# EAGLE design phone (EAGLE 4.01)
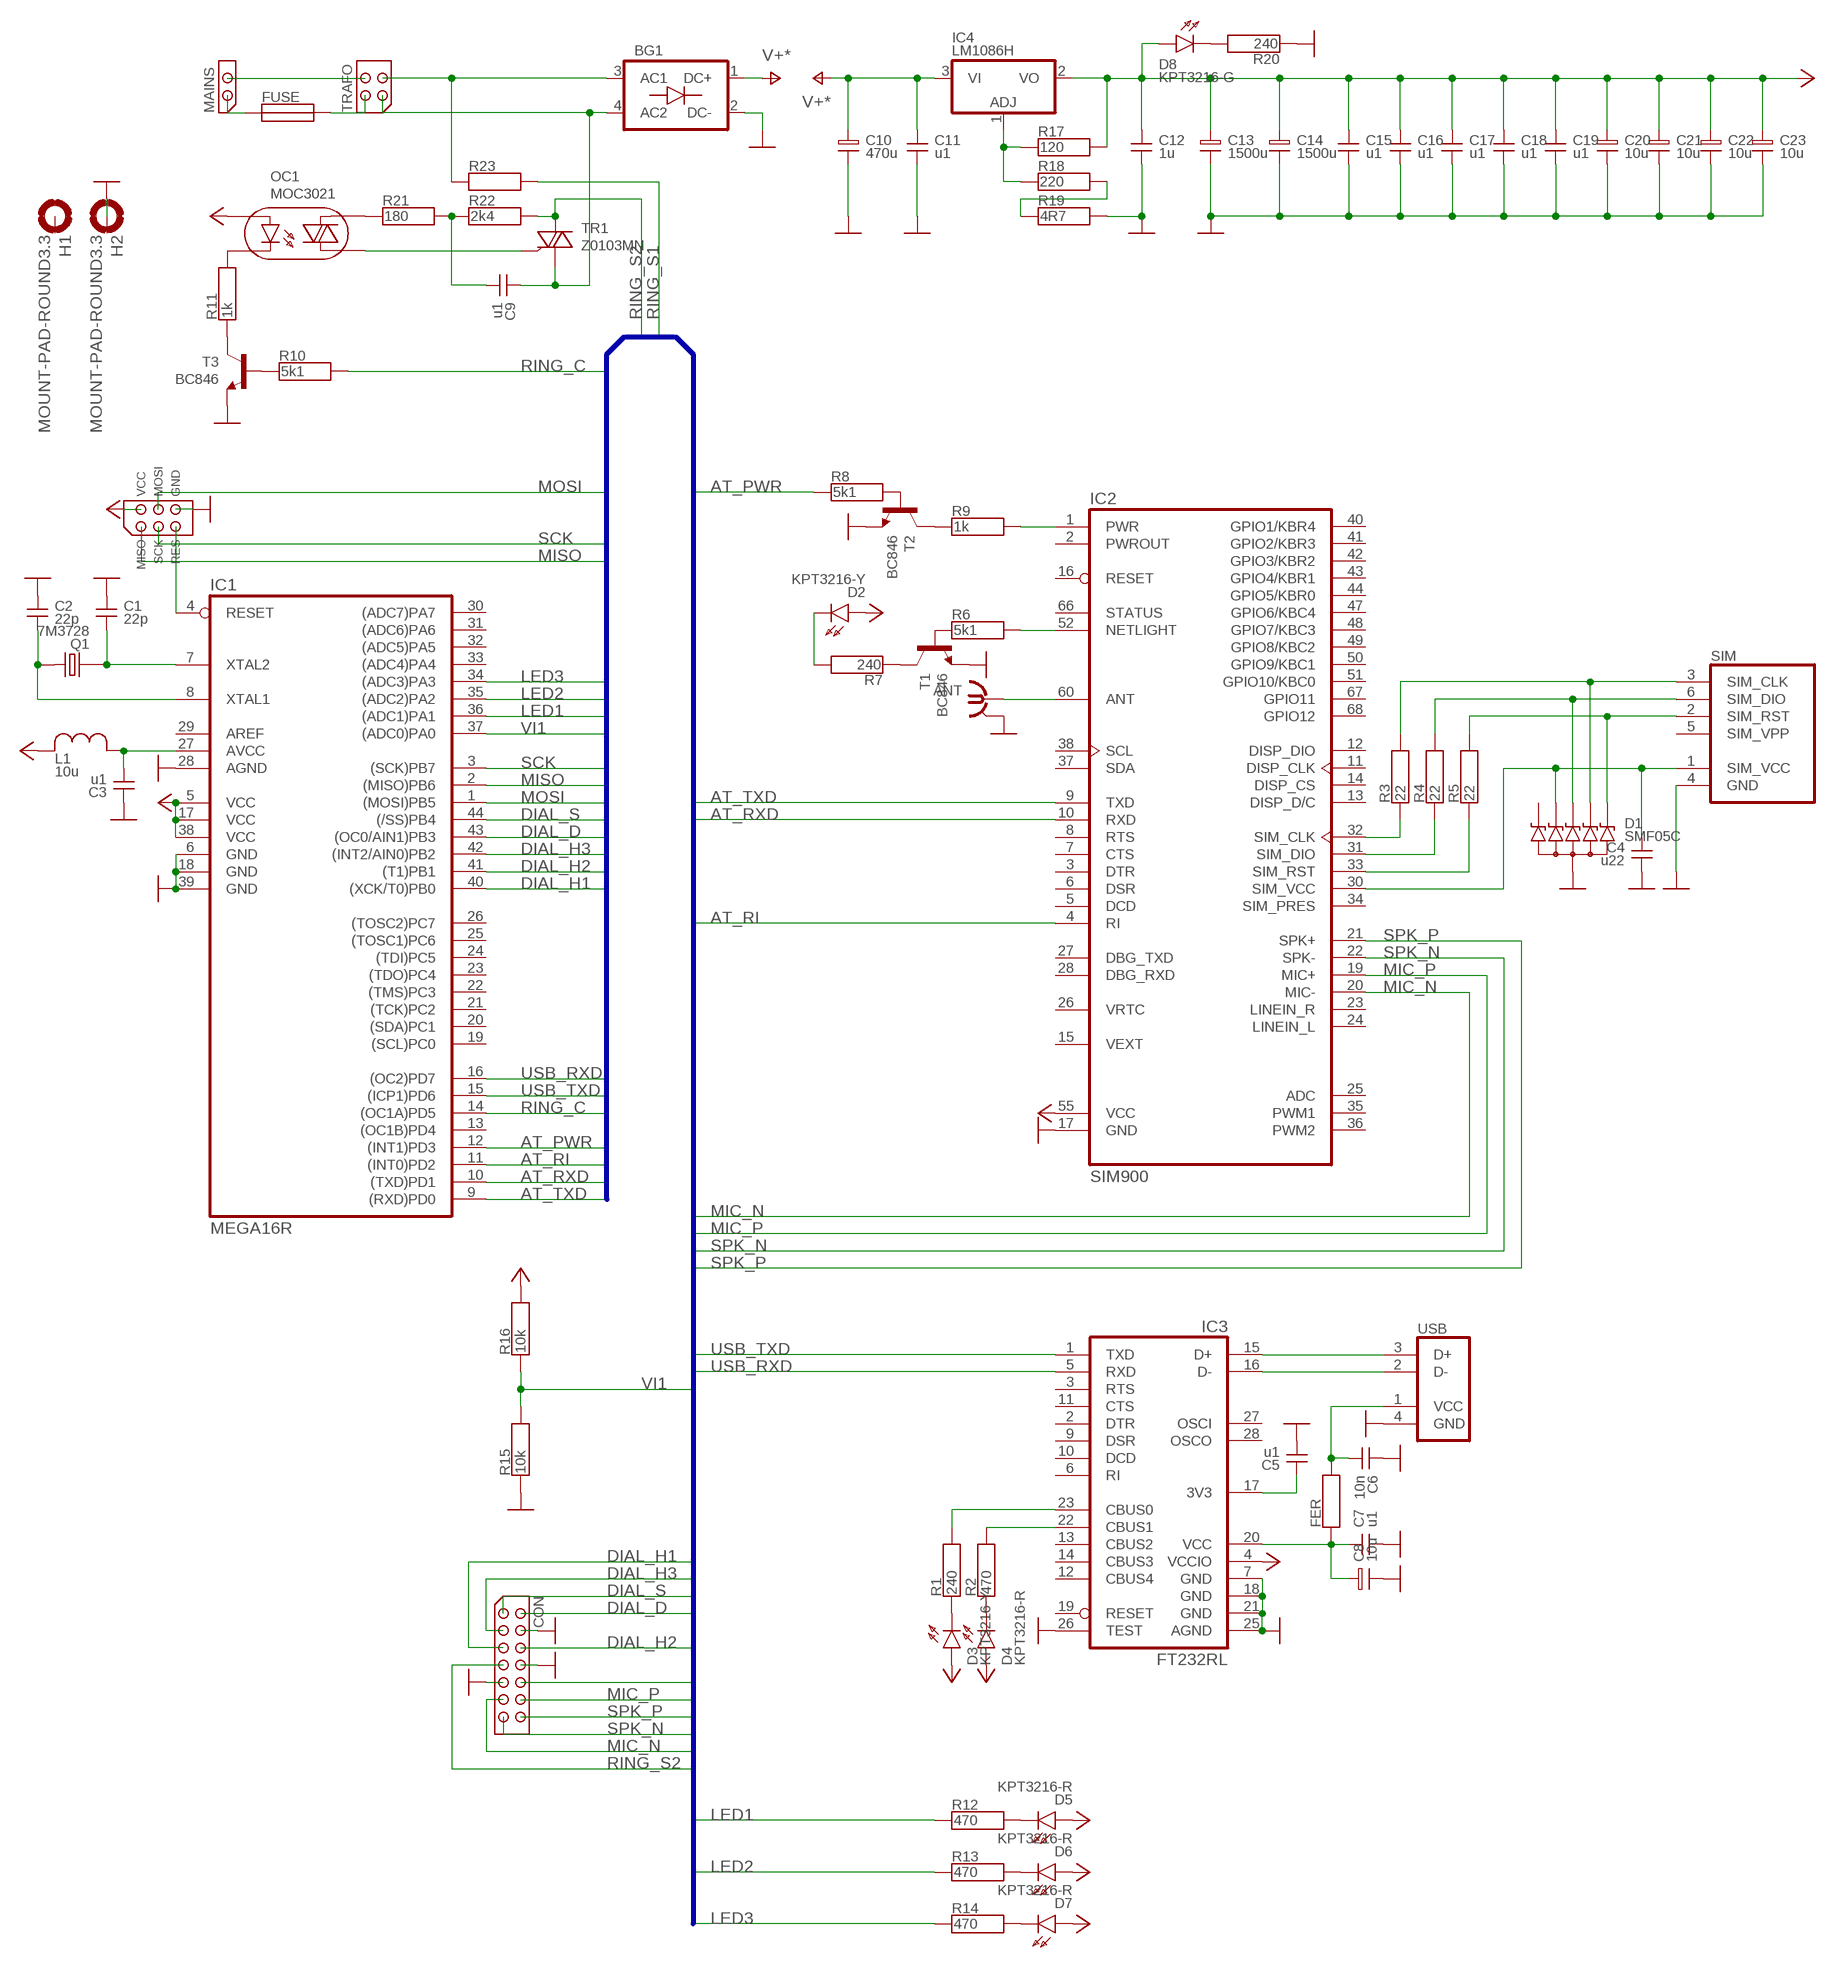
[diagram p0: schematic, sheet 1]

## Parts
ANT  SMAV  [SMAV]
BG1  BGR  [DFXXS]
C1  22p  CAP0805  [0805]
C2  22p  CAP0805  [0805]
C3  u1  CAP0805  [0805]
C4  u22  CAP0805  [0805]
C5  u1  CAP0805  [0805]
C6  10n  CAP0805  [0805]
C7  u1  CAP0805  [0805]
C8  10u  CTA3216  [3216]
C9  u1  CAP0805  [0805]
C10  470u  ELKH  [SMCH]
C11  u1  CAP0805  [0805]
C12  1u  CAP0805  [0805]
C13  1500u  ELKH  [SMCH]
C14  1500u  ELKH  [SMCH]
C15  u1  CAP0805  [0805]
C16  u1  CAP0805  [0805]
C17  u1  CAP0805  [0805]
C18  u1  CAP0805  [0805]
C19  u1  CAP0805  [0805]
C20  10u  CTA3216  [3216]
C21  10u  CTA3216  [3216]
C22  10u  CTA3216  [3216]
C23  10u  CTA3216  [3216]
CON  CON07X2  [CON07X2]
D1  SMF05C  DA5  [SC70-6]
D2  KPT3216-Y  LED1206  [1206]
D3  KPT3216-Y  LED1206  [1206]
D4  KPT3216-R  LED1206  [1206]
D5  KPT3216-R  LED1206  [1206]
D6  KPT3216-R  LED1206  [1206]
D7  KPT3216-R  LED1206  [1206]
D8  KPT3216-G  LED1206  [1206]
FER  RES1206  [1206]
FUSE  FUSE  [FUSE]
H1  MOUNT-PAD-ROUND3.3  [3,3-PAD]
H2  MOUNT-PAD-ROUND3.3  [3,3-PAD]
IC1  MEGA16R  [TQFP44]
IC2  SIM900  [PSP68]
IC3  FT232RL  [SSOP28]
IC4  LM1086H  LM317H  [TO220H]
ISP  ISP6  [CON03X2]
L1  10u  L1206  [1206]
MAINS  N42GP02  [N42GP02]
OC1  MOC3021  OCT  [DIL06]
Q1  7M3728  Q01S  [HC49S]
R1  240  RES0805  [0805]
R2  470  RES0805  [0805]
R3  22  RES0805  [0805]
R4  22  RES0805  [0805]
R5  22  RES0805  [0805]
R6  5k1  RES0805  [0805]
R7  240  RES0805  [0805]
R8  5k1  RES0805  [0805]
R9  1k  RES0805  [0805]
R10  5k1  RES0805  [0805]
R11  1k  RES0805  [0805]
R12  470  RES0805  [0805]
R13  470  RES0805  [0805]
R14  470  RES0805  [0805]
R15  10k  RES0805  [0805]
R16  10k  RES0805  [0805]
R17  120  RES0805  [0805]
R18  220  RES0805  [0805]
R19  4R7  RES0805  [0805]
R20  240  RES0805  [0805]
R21  180  RES0805  [0805]
R22  2k4  RES0805  [0805]
R23  RES03  [02P300IL]
SIM  SIM  [C70710M0060492]
T1  BC846  TSSMDN  [SOT23]
T2  BC846  TSSMDN  [SOT23]
T3  BC846  TSSMDN  [SOT23]
TR1  Z0103MN  TRS  [SOT223]
TRAFO  N42GP04  [N42GP04]
USB  USBBV  [USBBV]

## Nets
AC_6_1: BG1.3(AC1) R23.1 TRAFO.3
AC_6_2: BG1.4(AC2) C9.2 TR1.1(A1) TRAFO.1
AT_PWR: IC1.12((INT1)PD3) R8.1
AT_RI: IC1.11((INT0)PD2) IC2.4(RI)
AT_RXD: IC1.10((TXD)PD1) IC2.10(RXD)
AT_TXD: IC1.9((RXD)PD0) IC2.9(TXD)
AVCC: C3.1 IC1.27(AVCC) L1.2
DIAL_D: CON.2 IC1.43((OC0/AIN1)PB3)
DIAL_H1: CON.5 IC1.40((XCK/T0)PB0)
DIAL_H2: CON.6 IC1.41((T1)PB1)
DIAL_H3: CON.3 IC1.42((INT2/AIN0)PB2)
DIAL_S: CON.1 IC1.44((/SS)PB4)
GND: ANT.2(GND) BG1.2(DC-) C1.2 C2.2 C3.2 C4.1 C5.1 C6.2 C7.1 C8.-(N) C10.N C11.1 C12.1 C13.N C14.N C15.1 C16.1 C17.1 C18.1 C19.1 C20.-(N) C21.-(N) C22.-(N) C23.-(N) CON.4 CON.8 CON.9 D1.2(A) H2.B3,3(MOUNT) IC1.6(GND) IC1.18(GND) IC1.28(AGND) IC1.39(GND) IC2.17(GND) IC3.7(GND) IC3.18(GND) IC3.21(GND) IC3.25(AGND) IC3.26(TEST) ISP.6(GND) R15.1 R19.2 R20.1 SIM.4(GND) T1.2(E) T2.2(E) T3.2(E) USB.4(GND) ; supply symbol labelled GND*
LED1: IC1.36((ADC1)PA1) R12.1
LED2: IC1.35((ADC2)PA2) R13.1
LED3: IC1.34((ADC3)PA3) R14.1
MIC_N: CON.11 IC2.20(MIC-)
MIC_P: CON.12 IC2.19(MIC+)
MISO: IC1.2((MISO)PB6) ISP.1(MISO)
MOSI: IC1.1((MOSI)PB5) ISP.4(MOSI)
N$1: C2.1 IC1.8(XTAL1) Q1.2
N$2: MAINS.2 TRAFO.4
N$3: C1.1 IC1.7(XTAL2) Q1.1
N$4: D2.2(C) R7.2
N$5: FUSE.1 MAINS.1
N$6: R7.1 T1.3(C)
N$7: R6.1 T1.1(B)
N$8: FUSE.2 TRAFO.2
N$9: R8.2 T2.1(B)
N$10: R9.1 T2.3(C)
N$11: C5.2 IC3.17(3V3)
N$12: IC2.1(PWR) R9.2
N$13: D3.2(C) R1.1
N$14: D4.2(C) R2.1
N$16: R10.1 T3.1(B)
N$17: IC2.32(SIM_CLK) R3.1
N$18: IC2.31(SIM_DIO) R4.1
N$19: IC2.33(SIM_RST) R5.1
N$20: D1.5(C4) R3.2 SIM.3(SIM_CLK)
N$21: D1.4(C3) R4.2 SIM.6(SIM_DIO)
N$22: D1.6(C5) R5.2 SIM.2(SIM_RST)
N$24: OC1.6(A1) R21.1
N$25: ANT.1 IC2.60(ANT)
N$26: C9.1 R21.2 R22.1
N$29: OC1.2(K) R11.2
N$30: D5.2(C) R12.2
N$31: D6.2(C) R13.2
N$32: D7.2(C) R14.2
N$36: R11.1 T3.3(C)
N$50: IC4.1(ADJ) R17.1 R18.1
N$52: R18.2 R19.1
N$58: D8.2(C) R20.2
NETLIGHT: IC2.52(NETLIGHT) R6.2
RES: IC1.4(RESET) ISP.5(RES)
RING_C: IC1.14((OC1A)PD5) R10.2
RING_S1: CON.10 R23.2
RING_S2: CON.7 R22.2 TR1.2(A2)
SCK: IC1.3((SCK)PB7) ISP.3(SCK)
SIM_VCC: C4.2 D1.3(C2) IC2.30(SIM_VCC) SIM.1(SIM_VCC)
SPK_N: CON.13 IC2.22(SPK-)
SPK_P: CON.14 IC2.21(SPK+)
TR1_G: OC1.4(A2) TR1.3(G)
USB_D+: IC3.15(D+) USB.3(D+)
USB_D-: IC3.16(D-) USB.2(D-)
USB_RED: IC3.22(CBUS1) R2.2
USB_RXD: IC1.16((OC2)PD7) IC3.5(RXD)
USB_TXD: IC1.15((ICP1)PD6) IC3.1(TXD)
USB_VCC1: C7.2 C8.+(P) FER.1 IC3.20(VCC)
USB_VCC2: C6.1 FER.2 USB.1(VCC)
USB_YEL: IC3.23(CBUS0) R1.2
V+: BG1.1(DC+) C10.P C11.2 IC4.3(VI) ; supply symbol labelled V+*
VCC: C12.2 C13.P C14.P C15.2 C16.2 C17.2 C18.2 C19.2 C20.+(P) C21.+(P) C22.+(P) C23.+(P) D2.1(A) D3.1(A) D4.1(A) D5.1(A) D6.1(A) D7.1(A) D8.1(A) IC1.5(VCC) IC1.17(VCC) IC1.38(VCC) IC2.55(VCC) IC3.4(VCCIO) IC4.2(VO) ISP.2(VCC) L1.1 OC1.1(A) R16.2 R17.2 ; supply symbol labelled VCC*
VI1: IC1.37((ADC0)PA0) R15.2 R16.1
Unconnected: D1.1(C1) H1.B3,3(MOUNT) IC1.13((OC1B)PD4) IC1.19((SCL)PC0) IC1.20((SDA)PC1) IC1.21((TCK)PC2) IC1.22((TMS)PC3) IC1.23((TDO)PC4) IC1.24((TDI)PC5) IC1.25((TOSC1)PC6) IC1.26((TOSC2)PC7) IC1.30((ADC7)PA7) IC1.31((ADC6)PA6) IC1.32((ADC5)PA5) IC1.33((ADC4)PA4) IC2.2(PWROUT) IC2.3(DTR) IC2.5(DCD) IC2.6(DSR) IC2.7(CTS) IC2.8(RTS) IC2.11(DISP_CLK) IC2.12(DISP_DIO) IC2.13(DISP_D/C) IC2.14(DISP_CS) IC2.15(VEXT) IC2.16(RESET) IC2.23(LINEIN_R) IC2.24(LINEIN_L) IC2.25(ADC) IC2.26(VRTC) IC2.27(DBG_TXD) IC2.28(DBG_RXD) IC2.34(SIM_PRES) IC2.35(PWM1) IC2.36(PWM2) IC2.37(SDA) IC2.38(SCL) IC2.40(GPIO1/KBR4) IC2.41(GPIO2/KBR3) IC2.42(GPIO3/KBR2) IC2.43(GPIO4/KBR1) IC2.44(GPIO5/KBR0) IC2.47(GPIO6/KBC4) IC2.48(GPIO7/KBC3) IC2.49(GPIO8/KBC2) IC2.50(GPIO9/KBC1) IC2.51(GPIO10/KBC0) IC2.66(STATUS) IC2.67(GPIO11) IC2.68(GPIO12) IC3.2(DTR) IC3.3(RTS) IC3.6(RI) IC3.9(DSR) IC3.10(DCD) IC3.11(CTS) IC3.12(CBUS4) IC3.13(CBUS2) IC3.14(CBUS3) IC3.19(RESET) IC3.27(OSCI) IC3.28(OSCO) SIM.5(SIM_VPP) TR1.4(A2)

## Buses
MISO,MOSI,SCK,AT_PWR,AT_RXD,AT_TXD,AT_RI,SPK_P,SPK_N,MIC_P,MIC_N,USB_RXD,USB_TXD,RING_C,RING_S1,RING_S2,DIAL_H[1..3],DIAL_D,DIAL_S,VI[1..2],LED[1..3]

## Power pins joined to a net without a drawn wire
AREF: IC1.29(AREF)
GND: ANT.3(GND) ANT.4(GND) ANT.5(GND) IC2.18(GND) IC2.29(GND) IC2.39(GND) IC2.45(GND) IC2.46(GND) IC2.53(GND) IC2.54(GND) IC2.58(GND) IC2.59(GND) IC2.61(GND) IC2.62(GND) IC2.63(GND) IC2.64(GND) IC2.65(GND) USB.5(GND) USB.6(GND)
VCC: IC2.56(VCC) IC2.57(VCC)

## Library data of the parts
ANT = connector:SMA
BG1 = discrete:BG
C1-C7 C9 C11 C12 C15-C19 = discrete:CAP0805
C8 C20-C23 = discrete:CTA3216
C10 C13 C14 = discrete:ELKH
CON = connector:CON07X2
D1 = discrete:DA5: SMF05C
D2-D8 = discrete:LED1206
FER = discrete:RES1206
FUSE = special:FUSE: Fuse:
H1 H2 = holes:MOUNT-PAD-ROUND: MOUNTING PAD, round
IC1 = atmel:MEGA16*R: MICROCONTROLLER 16 Kbytes FLASH, 512 bytes EEPROM, 1 Kbytes SRAM
IC2 = special:SIM900: SIMcom SIM900 GSM/GPRS Quad-Band Modem 850/900/1800/1900 MHz
IC3 = special:FT232R: FTDI USB to serial UART interface
IC4 = linear:LM317: 3-Terminal Positive Voltage Adjustable Regulator
ISP = atmel:ISP6
L1 = discrete:L1206
MAINS = connector:N42GP02
OC1 = discrete:OCT
Q1 = discrete:Q01S
R1-R22 = discrete:RES0805
R23 = discrete:RES03
SIM = connector:SIM: SIM Card Connector
T1-T3 = discrete:TSSMDN
TR1 = discrete:TRS
TRAFO = connector:N42GP04
USB = connector:USB

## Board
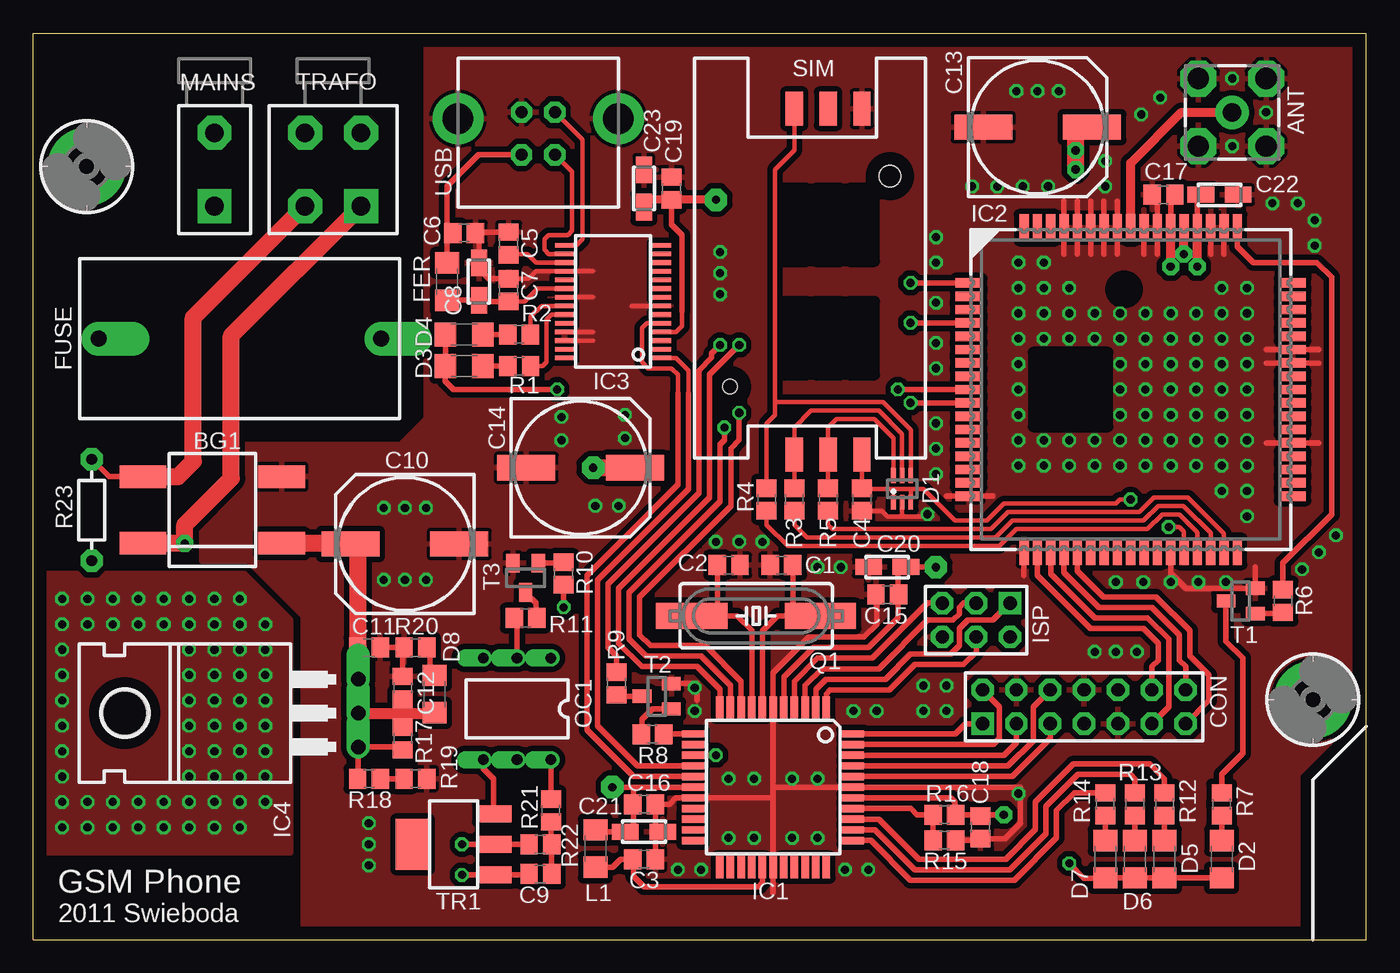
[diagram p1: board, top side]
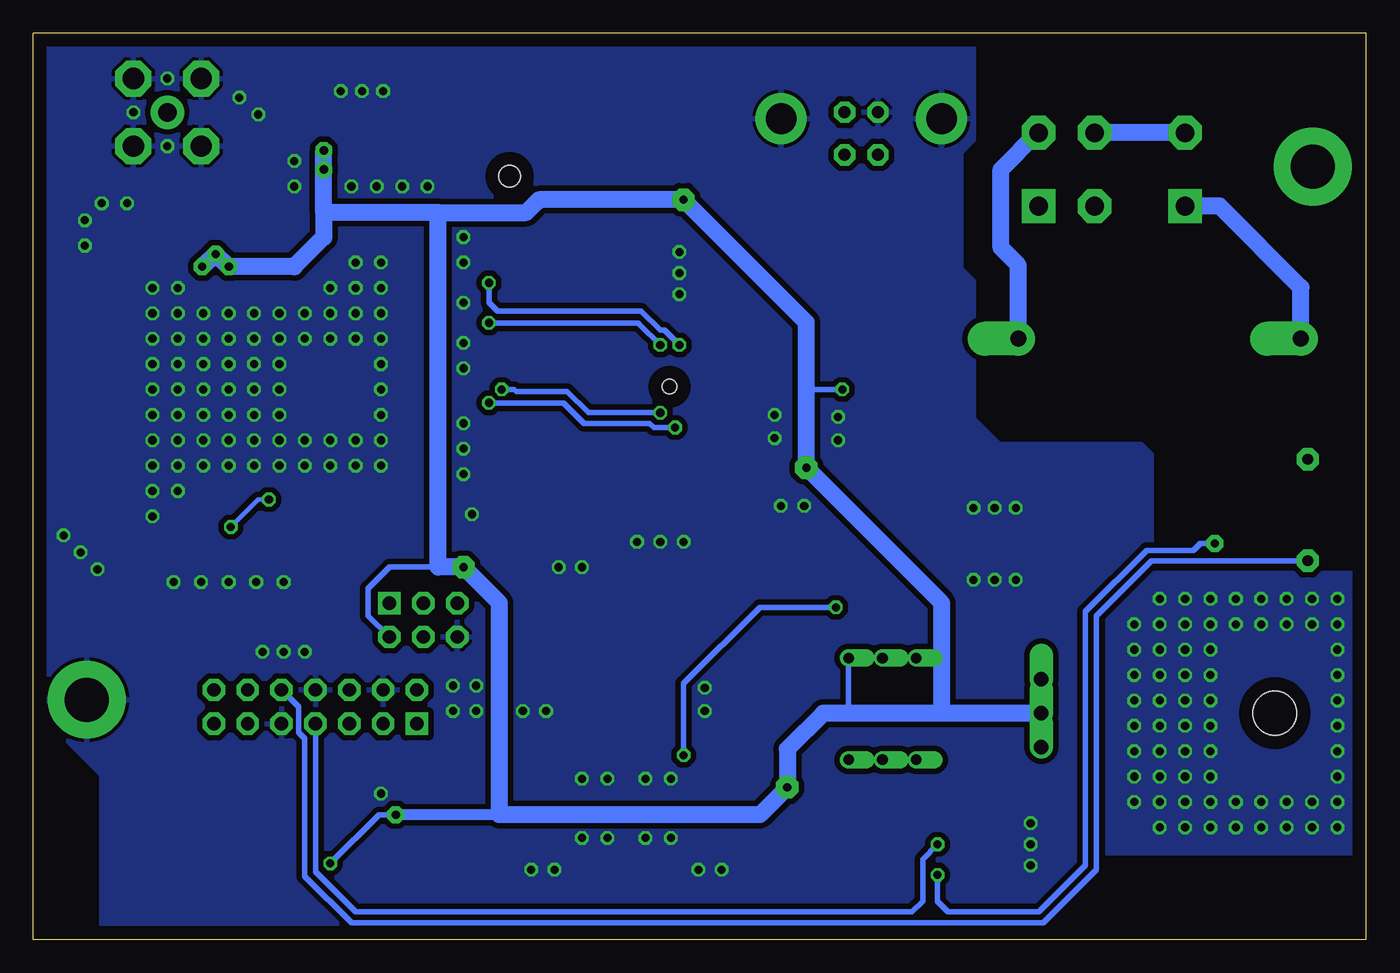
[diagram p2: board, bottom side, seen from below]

Size 100 x 68 mm. Coordinates in mm from the lower left corner, seen from the top.
Outline: 0,0 100,0 100,68 0,68 0,0
Copper layers used: Top, Bottom

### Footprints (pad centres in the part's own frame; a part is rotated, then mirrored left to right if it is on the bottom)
SMAV = drill 1.4 pad 2.5 round: 1 0,0 | drill 1.6 pad 2.7 octagon: 2 -2.54,2.54; 3 2.54,2.54; 4 -2.54,-2.54; 5 2.54,-2.54
DFXXS = smd 1.7 x 3.5: 1 -2.5,-5.2; 2 2.5,-5.2; 3 2.5,5.2; 4 -2.5,5.2
0805 = smd 1.3 x 1.5: 1 -0.85,0; 2 0.85,0
3216 = smd 2 x 1.2: + -1.4,0; - 1.4,0
SMCH = smd 4.35 x 1.9: N -4.08,0; P 4.08,0
CON07X2 = drill 1 pad 1.676 square: 1 0,0 | drill 1 pad 1.676 octagon: 2 0,2.54; 3 2.54,0; 4 2.54,2.54; 5 5.08,0; 6 5.08,2.54; 7 7.62,0; 8 7.62,2.54; 9 10.16,0; 10 10.16,2.54; 11 12.7,0; 12 12.7,2.54; 13 15.24,0; 14 15.24,2.54
SC70-6 = smd 0.35 x 1.1: 1 -0.65,-1; 2 0,-1; 3 0.65,-1; 4 0.65,1; 5 0,1; 6 -0.65,1
1206 = smd 1.6 x 1.8: 1 -1.4,0; 2 1.4,0
FUSE = drill 1.2 pad 2.54 offset: 1 -10.6,0; 2 10.6,0
3,3-PAD = drill 3.3 pad 5.842 round: B3,3 0,0
TQFP44 = smd 1.676 x 0.559: 1 -5.994,4; 2 -5.994,3.2; 3 -5.994,2.4; 4 -5.994,1.6; 5 -5.994,0.8; 6 -5.994,0; 7 -5.994,-0.8; 8 -5.994,-1.6; 9 -5.994,-2.4; 10 -5.994,-3.2; 11 -5.994,-4; 23 5.994,-4; 24 5.994,-3.2; 25 5.994,-2.4; 26 5.994,-1.6; 27 5.994,-0.8; 28 5.994,0; 29 5.994,0.8; 30 5.994,1.6; 31 5.994,2.4; 32 5.994,3.2; 33 5.994,4 | smd 0.559 x 1.676: 12 -4,-5.994; 13 -3.2,-5.994; 14 -2.4,-5.994; 15 -1.6,-5.994; 16 -0.8,-5.994; 17 0,-5.994; 18 0.8,-5.994; 19 1.6,-5.994; 20 2.4,-5.994; 21 3.2,-5.994; 22 4,-5.994; 34 4,5.994; 35 3.2,5.994; 36 2.4,5.994; 37 1.6,5.994; 38 0.8,5.994; 39 0,5.994; 40 -0.8,5.994; 41 -1.6,5.994; 42 -2.4,5.994; 43 -3.2,5.994; 44 -4,5.994
PSP68 = smd 2 x 0.7: 1 -12.15,8; 2 -12.15,7; 3 -12.15,6; 4 -12.15,5; 5 -12.15,4; 6 -12.15,3; 7 -12.15,2; 8 -12.15,1; 9 -12.15,0; 10 -12.15,-1; 11 -12.15,-2; 12 -12.15,-3; 13 -12.15,-4; 14 -12.15,-5; 15 -12.15,-6; 16 -12.15,-7; 17 -12.15,-8; 35 12.15,-8; 36 12.15,-7; 37 12.15,-6; 38 12.15,-5; 39 12.15,-4; 40 12.15,-3; 41 12.15,-2; 42 12.15,-1; 43 12.15,0; 44 12.15,1; 45 12.15,2; 46 12.15,3; 47 12.15,4; 48 12.15,5; 49 12.15,6; 50 12.15,7; 51 12.15,8 | smd 0.7 x 2: 18 -8,-12.15; 19 -7,-12.15; 20 -6,-12.15; 21 -5,-12.15; 22 -4,-12.15; 23 -3,-12.15; 24 -2,-12.15; 25 -1,-12.15; 26 0,-12.15; 27 1,-12.15; 28 2,-12.15; 29 3,-12.15; 30 4,-12.15; 31 5,-12.15; 32 6,-12.15; 33 7,-12.15; 34 8,-12.15; 52 8,12.15; 53 7,12.15; 54 6,12.15; 55 5,12.15; 56 4,12.15; 57 3,12.15; 58 2,12.15; 59 1,12.15; 60 0,12.15; 61 -1,12.15; 62 -2,12.15; 63 -3,12.15; 64 -4,12.15; 65 -5,12.15; 66 -6,12.15; 67 -7,12.15; 68 -8,12.15
SSOP28 = smd 0.348 x 1.397: 1 -4.135,-3.716; 2 -3.485,-3.716; 3 -2.835,-3.716; 4 -2.185,-3.716; 5 -1.535,-3.716; 6 -0.885,-3.716; 7 -0.235,-3.716; 8 0.415,-3.716; 9 1.065,-3.716; 10 1.715,-3.716; 11 2.365,-3.716; 12 3.015,-3.716; 13 3.665,-3.716; 14 4.315,-3.716; 15 4.315,3.596; 16 3.665,3.596; 17 3.015,3.596; 18 2.365,3.596; 19 1.715,3.596; 20 1.065,3.596; 21 0.415,3.596; 22 -0.235,3.596; 23 -0.885,3.596; 24 -1.535,3.596; 25 -2.185,3.596; 26 -2.835,3.596; 27 -3.485,3.596; 28 -4.135,3.596
TO220H = drill 1.1 pad 1.778 offset: 1 -2.54,0; 2 0,0; 3 2.54,0 | hole 3.3: 0,17.526
CON03X2 = drill 1 pad 1.676 square: 1 0,0 | drill 1 pad 1.676 octagon: 2 0,2.54; 3 2.54,0; 4 2.54,2.54; 5 5.08,0; 6 5.08,2.54
N42GP02 = drill 1.4 pad 2.54 square: 1 0,-2.75 | drill 1.4 pad 2.54 octagon: 2 0,2.75
DIL06 = drill 0.8 pad 1.27 offset: 1 -2.54,-3.81; 2 0,-3.81; 3 2.54,-3.81; 4 2.54,3.81; 5 0,3.81; 6 -2.54,3.81
HC49S = smd 5.334 x 1.93: 1 -4.826,0; 2 4.826,0
02P300IL = drill 0.8 pad 1.676 octagon: 1 -3.81,0; 2 3.81,0
C70710M0060492 = smd 2.54 x 1.3: 1 -12.97,-2.54; 2 -12.97,0; 3 -12.97,2.54; 4 12.97,-2.54; 5 12.97,0; 6 12.97,2.54 | hole 1.1: -7.89,7.36 | hole 1.6: 7.91,-4.64
SOT23 = smd 1 x 1.4: 1 -0.95,-1.1; 2 0.95,-1.1; 3 0,1.1
SOT223 = smd 1.27 x 2.54: 1 -2.3,-3.07; 2 0,-3.07; 3 2.3,-3.07 | smd 3.81 x 2.54: 4 0,3.07
N42GP04 = drill 1.4 pad 2.54 square: 1 2.1,-2.75 | drill 1.4 pad 2.54 octagon: 2 2.1,2.75; 3 -2.1,-2.75; 4 -2.1,2.75
USBBV = drill 0.9 pad 1.6 octagon: 1 1.25,2.71; 2 -1.25,2.71; 3 -1.25,-0.49; 4 1.25,-0.49 | drill 2.3 pad 3.81 round: 5 -6.02,0; 6 6.02,0

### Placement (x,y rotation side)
ANT  89.95,62.07 0 top
BG1  13.43,32.23 90 top
C1  56.14,28.1 180 top
C2  52.17,28.1 0 top
C3  45.82,6.03 0 top
C4  62.17,33.02 90 top
C5  35.66,52.23 270 top
C6  32.32,53.02 0 top
C7  35.66,48.74 270 top
C8  33.43,49.37 90 top
C9  38.04,4.92 180 top
C10  27.88,29.69 180 top
C11  25.18,21.91 180 top
C12  27.72,18.89 270 top
C13  75.34,60.96 0 top
C14  41.05,35.4 0 top
C15  64.07,25.88 0 top
C16  45.82,10.16 180 top
C17  84.79,55.88 0 top
C18  71.06,8.41 90 top
C19  47.88,56.36 270 top
C20  64.07,27.94 180 top
C21  45.82,8.1 0 top
C22  89,55.88 0 top
C23  45.82,56.36 90 top
CON  71.22,16.19 0 top
D1  65.18,33.81 0 top
D2  89.16,6.03 90 top
D3  32.32,43.02 0 top
D4  32.32,45.4 0 top
D5  84.87,6.03 90 top
D6  82.65,6.03 90 top
D7  80.42,6.03 90 top
D8  30.1,18.42 90 top
FER  31.05,49.37 90 top
FUSE  15.5,45.09 0 top
H1  4,58 0 top
H2  96,18 0 top
IC1  55.5,11.43 270 top
IC2  82.33,41.27 0 top
IC3  43.44,47.78 90 top
IC4  24.39,16.99 90 top
ISP  73.28,25.24 180 top
L1  42.17,6.83 270 top
MAINS  13.59,57.78 0 top
OC1  36.29,17.3 180 top
Q1  54.23,24.29 180 top
R1  36.45,43.02 0 top
R2  36.45,45.4 0 top
R3  57.09,33.02 90 top
R4  55.02,33.02 90 top
R5  59.63,33.02 90 top
R6  93.76,25.4 90 top
R7  89.16,10.16 270 top
R8  46.45,15.4 180 top
R9  43.75,19.21 90 top
R10  39.78,27.46 270 top
R11  36.93,24.13 180 top
R12  84.87,10.16 270 top
R13  82.65,10.16 270 top
R14  80.42,10.16 270 top
R15  68.36,7.46 180 top
R16  68.36,9.37 0 top
R17  27.72,15.08 90 top
R18  25.18,12.07 0 top
R19  28.67,12.07 0 top
R20  28.67,21.91 0 top
R21  38.83,9.68 270 top
R22  38.04,7.14 180 top
R23  4.38,32.23 270 top
SIM  59.63,49.37 90 top
T1  90.58,25.4 90 top
T2  46.77,18.26 90 top
T3  36.93,27.15 180 top
TR1  31.53,7.14 90 top
TRAFO  22.48,57.78 0 top
USB  37.88,61.59 180 top

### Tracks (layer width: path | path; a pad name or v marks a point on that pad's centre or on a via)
AC_6_1
  Top 0.406: R23.1 5.69,34.73 BG1.3 | 20.36,55.03 TRAFO.3
  Top 1.27: BG1.3 10.85,34.73 12,35.88 12,46.67 20.36,55.03
AC_6_2  (via drill 0.61 pad 0.81, 0.61 pad 1.27)
  Top 0.406: C9.2 37.09,4.92 37.09,4.84 TR1.1 v32.16,4.84
  Top 1.27: BG1.4 v11.37,29.73 11.37,31.11 14.86,34.61 14.86,45.31 TRAFO.1
  Bottom 0.406: v32.16,4.84 32.16,2.86 31.37,2.06 24.54,2.06 21.05,5.56 21.05,24.61 16.45,29.21 12.95,29.21 12.44,29.73 v11.37,29.73
AT_PWR
  Top 0.406: R8.1 47.24,15.4 47.24,15.43 IC1.12
AT_RI  (via drill 0.61 pad 0.81)
  Top 0.406: IC1.11 51.5,18.76 49.78,20.48 45.66,20.48 43.91,22.23 43.91,26.35 50.74,33.18 50.74,42.39 v52.96,44.61 | v65.82,46.27 IC2.4
  Bottom 0.406: v65.82,46.27 54.63,46.27 54.55,46.2 | v52.96,44.61 54.55,46.2 | 54.55,46.2
AT_RXD  (via drill 0.61 pad 0.81)
  Top 0.406: IC1.10 52.3,19.07 50.1,21.27 45.98,21.27 44.7,22.54 44.7,26.04 | 44.7,26.04 51.53,32.86 51.53,37.15 51.85,37.47 v51.85,38.42 | v65.82,40.27 IC2.10 | 44.7,26.04
  Bottom 0.406: v65.82,40.27 60.22,40.27 58.67,38.73 53.75,38.73 53.44,38.42 v51.85,38.42
AT_TXD  (via drill 0.61 pad 0.81)
  Top 0.406: IC1.9 53.1,19.39 50.42,22.07 46.29,22.07 45.5,22.86 45.5,25.72 52.33,32.54 52.33,36.83 52.96,37.47 v52.96,39.53 | v64.87,41.27 IC2.9
  Bottom 0.406: v64.87,41.27 63.91,41.27 63.75,41.12 59.94,41.12 58.36,39.53 v52.96,39.53
AVCC
  Top 0.406: L1.2 43.46,5.43 44.07,6.03 44.86,6.03 C3.1 44.97,5.93 45.02,5.87 45.02,4.76 45.82,3.97 54.39,3.97 54.7,4.28 IC1.27
DIAL_D
  Top 0.406: IC1.43 72.03,14.63 72.49,15.08 72.49,17.46 CON.2 | CON.2
DIAL_H1
  Top 0.406: IC1.40 73.44,12.23 76.3,15.08 CON.5
DIAL_H2
  Top 0.406: IC1.41 73.13,13.03 75.03,14.92 75.03,17.46 CON.6 | CON.6
DIAL_H3
  Top 0.406: IC1.42 72.82,13.83 73.76,14.76 CON.3
DIAL_S
  Top 0.406: IC1.44 69.18,15.43 69.95,16.19 CON.1
GND  (via drill 0.61 pad 0.81)
  Top 0.356: C4.1 63.65,32.17 64.07,31.75 65.18,31.75 | D1.2 | 65.18,31.75 D1.2 | 65.18,31.75 66.93,31.75 v67.09,31.91 | C7.1 37.14,49.59 37.7,50.15 IC3.18 42.01,50.15 | 44.86,47.55 IC3.7 | IC3.21 42.01,48.2 | IC3.25 42.01,45.6 | IC3.26 42.01,44.95
  Top 0.406: IC1.6 55.5,20 58.2,22.7 62.33,22.7 63.28,23.65 63.28,25.88 C15.1 | C7.1 34.17,49.59 33.43,50.32 C8.- 33.43,53.02 | C6.2 33.12,53.02 | C6.2 | 33.43,53.02 C6.2 | 33.43,53.02 | C5.1 33.43,53.08 33.43,53.02 | R15.1 71.06,7.46 C18.1 72.91,7.56 74.07,8.73 74.07,11.43 IC1.39 55.5,11.43 | C21.- | 46.67,8.1 C16.1 47.72,10.16 48.19,10.63 IC1.18 55.5,10.63 55.5,11.43 | 46.67,8.1 C21.- | C3.2 46.61,6.03 | C3.2 | C3.2 46.67,8.1 | C3.2 | 27.72,21.91 | 27.72,21.91 R20.1 | 27.72,21.91 C11.1 | 27.72,21.91 | R20.1 27.88,21.91 | C12.1 27.72,21.91 | 27.72,21.91 R20.1 | 68.52,33.27 IC2.17 72.01,33.27 | 74.33,27.3 IC2.18 | IC2.29 85.33,27.46 85.34,27.46 86.46,26.35 T1.2 91.68,27.94 | 77.33,55.4 IC2.65 77.33,51.44 | 78.33,55.4 IC2.64 78.33,51.44 | 79.33,55.4 IC2.63 79.33,51.44 | 80.33,55.4 IC2.62 80.33,51.44 | 81.33,55.4 IC2.61 81.33,51.44 | 83.33,51.44 IC2.59 | C17.1 84.33,55.88 IC2.58 84.33,51.44 | 88.33,51.44 IC2.54 | 89.33,51.44 IC2.53 | 92.49,37.27 IC2.39 96.46,37.27 | 92.49,43.27 IC2.45 96.46,43.27 | 92.49,44.27 IC2.46 96.46,44.27 | 55.5,3.49 IC1.28 55.5,11.43 | IC1.6 | 55.5,11.43 IC1.6 | T2.2 49.78,19.21 49.78,17.94
  other vias: 73.92,50.8 73.92,48.9 75.82,50.8 75.82,48.9 77.72,48.9 73.92,46.99 75.82,46.99 77.72,46.99 79.63,46.99 81.53,46.99 83.44,46.99 85.34,46.99 87.25,46.99 73.92,45.09 75.82,45.09 77.72,45.09 79.63,45.09 81.53,45.09 81.53,43.18 73.92,43.18 73.92,41.27 73.92,39.37 73.92,37.47 75.82,37.47 77.72,37.47 79.63,37.47 81.53,37.47 81.53,39.37 81.53,41.27 83.44,45.09 83.44,43.18 83.44,41.27 83.44,39.37 83.44,37.47 85.34,45.09 85.34,43.18 85.34,41.27 85.34,39.37 85.34,37.47 87.25,45.09 87.25,43.18 87.25,41.27 87.25,39.37 87.25,37.47 89.16,48.9 91.06,48.9 89.16,46.99 91.06,46.99 89.16,45.09 91.06,45.09 89.16,43.18 91.06,43.18 89.16,41.27 91.06,41.27 89.16,39.37 91.06,39.37 89.16,37.47 91.06,37.47 89.16,33.66 91.06,33.66 91.06,35.56 89.16,35.56 87.25,35.56 85.34,35.56 83.44,35.56 81.53,35.56 79.63,35.56 91.06,31.75 95.19,27.78 77.72,35.56 75.82,35.56 73.92,35.56 96.46,29.05 97.73,30.32 67.72,34.92 67.72,36.83 67.72,38.73 67.72,42.86 67.72,44.77 67.72,47.78 67.72,50.8 67.72,52.7 80.42,56.52 70.42,56.52 72.33,56.52 74.23,56.52 76.14,56.52 80.42,58.42 92.49,62.07 89.95,59.53 89.95,64.61 83.12,61.91 84.55,63.18 92.97,55.24 94.87,55.24 96.14,53.98 96.14,52.07 73.76,63.66 75.34,63.66 76.93,63.66 51.53,51.59 51.53,50.01 51.53,48.42 39.62,37.47 39.62,39.21 44.39,39.37 44.39,37.62 43.91,32.54 42.16,32.54 26.29,32.38 27.88,32.38 29.47,32.38 26.29,26.99 27.88,26.99 29.47,26.99 51.21,29.84 52.96,29.84 54.71,29.84 58.83,27.94 60.58,27.94 49.63,18.89 49.63,17.14 61.53,17.14 63.28,17.14 68.52,19.05 66.77,19.05 66.77,17.14 68.52,17.14 52.17,12.06 54.07,12.06 56.93,12.06 58.83,12.06 56.93,7.62 58.83,7.62 52.17,7.62 54.07,7.62 60.9,5.24 62.64,5.24 50.1,5.24 48.36,5.24 25.18,7.14 25.18,5.56 25.18,8.73 81.22,26.83 73.91,10.95 83.28,26.83 79.63,21.59 81.22,21.59 82.81,21.59 85.35,26.83 87.41,26.83 89.47,26.83
  pour Top (isolate 0.406): 99.95,67.94 100.11,17.62 94.87,12.38 94.87,0 20.26,0 20.26,24.29 16.13,28.42 12.64,28.42 12.64,37.15 27.56,37.15 29.47,39.05 29.47,67.94
  pour Bottom (isolate 0.406): 99.95,67.94 99.95,17.46 94.87,12.38 94.87,0 26.45,0 20.89,5.56 20.89,24.45 16.29,29.05 16.13,29.05 16.13,36.35 16.92,37.15 27.56,37.15 29.47,39.05 29.47,49.37 30.42,50.32 30.42,59.05 29.47,60.01 29.47,67.94
LED1
  Top 0.406: IC1.36 63.46,9.03 66.45,6.03 72.96,6.03 75.19,8.26 75.19,10.32 78.04,13.18 83.76,13.18 84.87,12.06 R12.1
LED2
  Top 0.406: IC1.35 63.14,8.23 66.14,5.24 73.28,5.24 75.98,7.94 75.98,10 78.36,12.38 82.33,12.38 82.65,12.06 R13.1
LED3
  Top 0.406: IC1.34 62.83,7.43 65.82,4.45 73.6,4.45 76.77,7.62 76.77,9.68 78.1,11.01 R14.1
MIC_N
  Top 0.406: IC2.20 76.33,27.43 79.63,24.13 83.6,24.13 85.19,22.54 85.19,17.46 CON.11
MIC_P
  Top 0.406: IC2.19 75.33,27.32 79.31,23.34 83.28,23.34 84.39,22.23 84.39,20.95 83.92,20.48 CON.12
MISO
  Top 0.406: IC1.2 58.7,18.76 59.47,19.53 63.91,19.53 65.82,21.43 68.83,21.43 69.47,22.07 69.47,23.34 70.11,23.97 72.01,23.97 ISP.1 | ISP.1
MOSI
  Top 0.406: IC1.1 59.5,18.45 59.79,18.73 64.23,18.73 66.14,20.64 69.79,20.64 70.74,21.59 70.74,22.54 | 70.74,22.54 | 70.74,22.54 ISP.4
N$1
  Top 0.406: IC1.8 53.9,23.19 52.8,24.29 51.37,24.29 | 51.32,24.29 C2.1 | 51.37,24.29 51.32,24.29 | 51.37,24.29 | 49.47,24.29 | 49.47,24.29 Q1.2 | 51.32,24.29 49.47,24.29
N$2
  Bottom 0.406: TRAFO.4 20.42,60.53 20.42,60.48
  Bottom 1.27: MAINS.2 20.42,60.53
N$3
  Top 0.406: IC1.7 54.7,23.17 55.82,24.29 | 55.82,24.29 | 56.98,24.29 C1.1 | 55.82,24.29 56.98,24.29 | Q1.1 | 56.98,24.29 Q1.1
N$4
  Top 0.406: 89.16,7.62 | D2.2 89.16,7.62 | 89.16,7.62 R7.2
N$5
  Bottom 1.27: FUSE.1 4.89,48.93 11,55.03 MAINS.1
N$6
  Top 0.406: 90.74,21.11 89.48,22.37 T1.3 | 89.16,10.95 R7.1 89.16,12.38 90.74,13.97 90.74,21.11 | 90.74,21.11
N$7
  Top 0.406: R6.1 93.76,24.61 | R6.1 | T1.1 93.76,24.45 R6.1
N$8
  Bottom 0.406: 24.65,60.53 TRAFO.2
  Bottom 1.27: FUSE.2 26.09,50.6 27.4,51.91 27.4,57.78 24.65,60.53
N$9
  Top 0.406: T2.1 46.45,17.31 45.66,16.51 45.66,15.4 R8.2
N$10
  Top 0.406: R9.1 43.75,18.26 T2.3
N$11
  Top 0.356: IC3.17 37.72,50.8 37.09,51.44 35.66,51.44 C5.2
N$12  (via drill 0.61 pad 0.81)
  Top 0.406: R9.2 43.75,21.27 43.12,21.91 43.12,26.67 49.94,33.5 49.94,42.7 50.9,43.66 50.9,43.97 v51.53,44.61 | v65.82,49.27 IC2.1
  Bottom 0.406: v65.82,49.27 65.82,47.78 65.18,47.15 54.39,47.15 52.96,45.72 52.64,45.72 v51.53,44.61
N$13
  Top 0.406: D3.2 R1.1
N$14
  Top 0.406: D4.2 33.75,45.4 | 33.75,45.4 R2.1 | 33.75,45.4
N$16
  Top 0.406: R10.1 | T3.1 39.78,28.25 R10.1
N$17
  Top 0.356: R3.1 57.09,31.11 58.04,30.16 72.17,30.16 73.44,31.43 83.28,31.43 84.39,32.54 86.3,32.54 88.33,30.51 IC2.32
N$18
  Top 0.356: R4.1 55.02,31.11 56.61,29.53 72.49,29.53 73.76,30.8 83.6,30.8 84.71,31.91 | IC2.31 87.33,30.56 85.98,31.91 84.71,31.91 | 84.71,31.91
N$19
  Top 0.356: R5.1 59.63,31.11 59.94,30.8 71.85,30.8 73.12,32.07 82.96,32.07 84.08,33.18 86.61,33.18 89.33,30.46 IC2.33
N$20
  Top 0.356: D1.5 65.18,37.94 63.44,39.69 58.36,39.69 57.09,38.42 | SIM.3 57.09,36.35 | 57.09,38.42 | SIM.3 57.09,38.42 | R3.2 | SIM.3 | R3.2 SIM.3
N$21
  Top 0.356: D1.4 65.83,38.24 63.75,40.32 55.66,40.32 | 55.02,33.97 | R4.2 55.02,33.97 | 57.09,59.21 SIM.6 | 55.02,33.97 55.02,38.73 55.66,39.37 55.66,40.32 | 57.09,59.21 | 55.66,40.32 55.66,57.78 57.09,59.21
  Top 0.406: 55.02,33.97
N$22
  Top 0.356: D1.6 64.53,37.64 63.12,39.05 60.26,39.05 59.63,38.42 SIM.2 R5.2
N$24
  Top 0.406: OC1.6 | OC1.6 | R21.1 | R21.1 OC1.6
N$25
  Top 0.686: IC2.60 82.33,58.26 86.14,62.07 ANT.1
N$26
  Top 0.406: 38.83,7.14 R21.2 | 38.83,7.14 | 38.83,7.14 R22.1 | R22.1 | C9.1 R22.1 | R22.1 38.83,7.14
N$29
  Top 0.406: R11.2 | OC1.2 36.29,24.13 R11.2
N$30
  Top 0.406: D5.2 84.87,7.46 | 84.87,7.46 R12.2 | 84.87,7.46
N$31
  Top 0.406: D6.2 R13.2
N$32
  Top 0.406: D7.2 80.42,7.62 | 80.42,7.62 R14.2 | 80.42,7.62
N$36
  Top 0.406: T3.3 36.93,25.56 37.4,25.56 37.72,25.24 37.72,24.13 R11.1 | R11.1
N$50
  Top 0.406: R17.1 | IC4.1 27.72,14.45 R17.1 | 24.38,12.06 | R18.1 24.38,12.06 | IC4.1 | 24.38,12.06 IC4.1
N$52
  Top 0.406: 27.72,12.06 | 27.72,12.06 R19.1 | R18.2 27.72,12.06 | 27.72,12.06
N$58
  Top 0.406: D8.2 29.78,19.82 29.78,21.91 R20.2
NETLIGHT
  Top 0.406: IC2.52 90.33,52.01 91.54,50.8 96.3,50.8 97.41,49.69 97.41,31.91 93.76,28.26 R6.2
RAD  (via drill 0.61 pad 0.81)
  other vias: 2.16,12.22 2.16,14.13 2.16,16.03 2.16,17.94 2.16,19.84 2.16,21.75 2.16,23.65 4.06,23.65 5.97,23.65 9.78,23.65 11.68,23.65 15.5,23.65 17.4,23.65 13.59,23.65 7.88,23.65 15.5,25.56 5.97,25.56 4.06,25.56 7.88,25.56 2.16,25.56 13.59,25.56 11.68,25.56 9.78,25.56 9.78,10.32 7.88,10.32 9.78,8.41 7.88,8.41 5.97,8.41 5.97,10.32 4.06,10.32 2.16,10.32 4.06,8.41 2.16,8.41 17.4,12.22 15.5,12.22 13.59,12.22 11.68,12.22 15.5,14.13 17.4,14.13 11.68,14.13 13.59,14.13 11.68,10.32 13.59,10.32 13.59,8.41 11.68,8.41 15.5,10.32 15.5,8.41 17.4,10.32 17.4,21.75 15.5,21.75 17.4,19.84 15.5,19.84 17.4,17.94 15.5,17.94 17.4,16.03 15.5,16.03 13.59,17.94 11.68,17.94 13.59,21.75 11.68,21.75 13.59,19.84 11.68,19.84 13.59,16.03 11.68,16.03
  pour Bottom (isolate 0.406): 0.1,27.46 16.13,27.46 19.46,24.13 19.46,6.51 0.1,6.51
  pour Top (isolate 0.406): 0.1,27.46 15.81,27.46 19.3,23.97 19.3,6.51 0.1,6.51
RES
  Top 0.406: IC1.4 57.1,19.38 58.83,21.11 62.96,21.11 67.09,25.24 ISP.5 | ISP.5
RING_C  (via drill 0.61 pad 0.81)
  Top 0.406: v39.78,24.92 R10.2 | IC1.14 v51.21,13.83
  Bottom 0.406: v39.78,24.92 45.5,24.92 51.21,19.21 v51.21,13.83
RING_S1
  Bottom 0.406: CON.10 80.11,17.46 80.11,15.56 79.63,15.08 79.63,4.76 76.14,1.27 24.23,1.27 20.26,5.24 20.26,24.29 16.13,28.42 R23.2
RING_S2  (via drill 0.61 pad 0.81)
  Top 0.406: R22.2 37.24,7.14 | R22.2 | TR1.2 | TR1.2 R22.2 | v32.16,7.14 TR1.2
  Bottom 0.406: v32.16,7.14 33.27,6.03 33.27,2.86 34.07,2.06 75.82,2.06 78.84,5.08 CON.7
SCK
  Top 0.406: IC1.3 57.9,19.07 59.15,20.32 63.44,20.32 67.09,23.97 68.99,23.97 69.47,24.45 69.47,24.92 69.79,25.24 ISP.3 | ISP.3
SIM_VCC  (via drill 0.61 pad 0.81)
  Top 0.356: 62.17,36.2 SIM.1 | 62.17,36.2 | 62.17,33.81 | 62.17,33.81 C4.2 62.17,33.97 | 62.17,33.97 | 62.17,33.97 62.17,36.2 | D1.3 65.83,33.81 65.82,33.81 | 62.17,33.81 65.82,33.81 | IC2.30 86.33,30.61 85.98,30.96 v85.19,30.96 | v82.33,33.02 81.53,33.02 81.22,32.7 72.8,32.7 71.53,31.43 69.15,31.43 66.77,33.81 65.82,33.81
  Bottom 0.356: v85.19,30.96 83.12,33.02 v82.33,33.02
SPK_N
  Top 0.406: IC2.22 78.33,27.65 80.27,25.72 84.23,25.72 86.77,23.18 86.77,21.27 88.2,19.84 88.2,17.94 CON.13
SPK_P
  Top 0.406: IC2.21 77.33,27.54 79.95,24.92 83.92,24.92 85.98,22.86 85.98,20.95 86.46,20.48 CON.14
TR1_G
  Top 0.406: OC1.4 33.75,12.86 34.55,12.06 34.55,9.53 34.6,9.47 TR1.3
USB_D+
  Top 0.356: IC3.15 40.77,52.1 41.21,52.55 41.21,60.01 USB.3
USB_D-
  Top 0.356: IC3.16 38.66,51.45 38.35,51.75 38.35,52.55 38.67,52.86 40.1,52.86 40.42,53.18 40.42,57.63 39.16,58.88 USB.2
USB_RED
  Top 0.356: IC3.22 38.12,47.55 37.3,46.73 R2.2
USB_RXD
  Top 0.305: 48.36,41.12 | 48.36,40.96 48.36,41.12
  Top 0.356: IC3.5 46.03,46.25 45.66,45.88 45.66,43.34 46.13,42.86 47.88,42.86 48.36,42.39 48.36,41.12
  Top 0.406: IC1.16 45.02,12.23 41.53,15.72 41.53,27.3 48.36,34.13 48.36,40.96
USB_TXD
  Top 0.356: IC3.1 48.2,43.65 49.15,42.7 49.15,40.96
  Top 0.406: IC1.15 45.33,13.03 42.32,16.03 42.32,26.99 49.15,33.81 49.15,40.96
USB_VCC1
  Top 0.356: IC3.20 37.83,48.85 36.87,47.89 C7.2
  Top 0.406: C7.2 33.43,47.89 33.43,47.94 | 33.43,47.94 C8.+ | C8.+ | FER.1 C8.+ | C8.+ 33.43,47.94
USB_VCC2
  Top 0.406: C6.1 31.53,53.02 | C6.1 | FER.2 31.05,53.02 | 31.05,53.02 C6.1 | 31.05,53.02 31.05,56.52 33.42,58.88 USB.1
USB_YEL
  Top 0.356: IC3.23 38.9,46.9 38.51,46.51 38.51,43.34 38.2,43.02 R1.2 37.24,43.02
V+
  Top 0.406: 23.75,29.69 | 23.75,29.69 C10.P 23.91,29.69 | 23.75,29.69 23.75,29.73 | 24.38,21.91 C11.2 | 23.91,29.69 | 24.38,29.69 23.91,29.69 | IC4.3
  Top 1.27: 23.75,29.73 BG1.1 | IC4.3 24.38,21.91 24.38,29.69
VCC  (via drill 0.61 pad 0.81, 0.61 pad 1.27, 0.61 pad 1.68)
  Top 0.356: IC3.4 48.23,45.6 48.67,46.04 48.67,47.15
  Top 0.406: IC1.5 56.3,19.69 58.52,21.91 62.64,21.91 64.87,24.13 64.87,25.88 | IC1.38 68.84,10.63 69.15,10.32 69.15,9.37 R16.2 71.06,9.37 | 71.06,9.37 C18.2 71.06,9.37 | 64.87,25.88 C15.2 | 64.87,25.88 64.87,27.94 C20.+ v67.72,27.94 | D2.1 84.9,4.63 84.87,4.6 D5.1 82.83,4.63 82.81,4.6 82.78,4.63 D6.1 80.45,4.63 80.42,4.6 | 80.42,4.6 | 47.88,55.24 | C19.2 47.88,55.24 | 47.88,55.24 47.88,53.66 48.67,52.86 48.67,47.15 | C23.+ 45.82,54.93 | C23.+ | 45.82,55.51 C23.+ | D4.1 D3.1 30.89,43.02 30.89,41.91 31.53,41.27 v39.31,41.27 | 45.02,11.43 IC1.17 | 45.02,11.43 45.02,10.16 | 45.02,10.16 C16.2 | 45.02,10.16 45.02,8.1 44.39,8.1 | 44.39,8.1 C21.+ | 44.39,8.1 | L1.1 42.16,8.26 | L1.1 | 44.39,8.1 42.16,8.1 L1.1 | C12.2 | C12.2 27.72,16.99 R17.2 | R17.2 27.72,15.88 | R17.2 | 30.1,16.99 D8.1 | D8.1 | 30.1,16.99 | v43.44,11.43 45.02,11.43 | v72.8,9.37 71.06,9.37 | 80.42,4.6 D7.1 | v77.72,5.71 78.84,4.6 80.42,4.6 | 85.66,55.88 C17.2 85.33,55.88 IC2.57 | IC2.55 87.33,55.88 C22.+ | 78.2,60.96 C13.P | C14.P 45.18,35.4 | C14.P
  Top 0.61: 45.82,55.51 C19.2 v51.21,55.51
  Top 0.686: v85.33,50.48 IC2.57 | v86.33,51.44 IC2.56 | v87.33,50.48 IC2.55
  Top 0.813: IC4.2 27.72,16.99 30.1,16.99
  Top 1.27: 78.2,60.96 v78.2,59.21 v78.2,57.78 | v42.01,35.4 C14.P
  Bottom 0.356: 31.85,16.99
  Bottom 0.406: v72.8,9.37 | v72.8,9.37 74.07,9.37 v77.72,5.71 | ISP.2 74.87,24.29 74.87,26.35 73.28,27.94 69.63,27.94 | v86.33,51.44 86.3,51.44 | 42.01,41.27 v39.31,41.27 | OC1.1 | OC1.1 | 38.83,16.99 OC1.1
  Bottom 0.813: 65.03,9.37 v72.8,9.37
  Bottom 1.27: v86.33,51.44 v85.33,50.48 80.42,50.48 78.2,52.7 78.2,54.55 | 86.3,51.44 v87.33,50.48 | v78.2,59.21 v78.2,57.78 78.2,54.55 | 31.85,16.99 31.85,25.24 v42.01,35.4 42.01,41.27 42.01,46.3 v51.21,55.51 62.06,55.51 | 31.85,16.99 38.83,16.99 40.74,16.99 43.44,14.29 v43.44,11.43 45.5,9.37 65.03,9.37 65.03,25.24 v67.72,27.94 69.63,27.94 69.63,54.55 | IC4.2 31.85,16.99 | 69.63,54.55 78.2,54.55 | 69.63,54.55 63.02,54.55 62.17,55.4
VI1
  Top 0.406: IC1.37 65.83,9.83 66.3,9.37 R16.1 | R16.1 67.56,9.37 | R16.1 R15.2 67.41,7.46

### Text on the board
tNames: GSM Phone | 2011 Swieboda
